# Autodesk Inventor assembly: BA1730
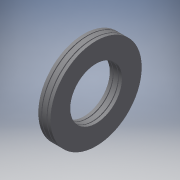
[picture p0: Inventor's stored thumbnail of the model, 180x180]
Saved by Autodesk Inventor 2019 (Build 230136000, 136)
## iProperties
Category: PARTsolutions
Company: MISUMI
Created: 2023-09
Part Number: BA1730
Catalog Web Link: www.cadenas.de
Description: BA_ _ _ _ _-Thrust Needle Roller Bearings with Retainers
Vendor: MISUMI
Document SubType Name: Assembly
Designer: psAdmin
Manufacturer: MISUMI
Mass: 1.86807 g
Surface Area: 34.7146 cm^2
Volume: 1.86807 cm^3
Density: 1 g/cm^3
Title: BA1730
Author: Cadenas PARTsolutions
Comments: Thrust Needle Roller Bearings with Retainers
PSOL_IDENT_0: {$CADENAS_DATA/23d-libs/misumi/metric/12_bearing_holders/ba1024_asmtab.prj},171 {VTYP=3D},{STYP=ASST
PSOL_IDENT_1: AB},{NB=BA1730},{LINA=BA1730},{NN=BA_ _ _ _ _},{DATE=03.06.2021 05:35:41},{GEOMDATE=19.10.2020 19:34
PSOL_IDENT_2: :04},{VERSION=},{LINEID=40},{WBVAR=},{WBNUMERIC=}  {NB=BA1730},{LINA=BA1730},{KT=DUMMY},{PN=BA1730},
PSOL_IDENT_3: {DD=17},{D=30},{B=2},{F=29.0},{F1=19.0},{DD1=17},{D1=30},{B1=1},{PPATH=ba1024_asmtpl.prj}
NB: BA1730
NN: BA_ _ _ _ _
NT: Thrust Needle Roller Bearings with Retainers
NBSYN: $PN.
LINA: BA1730
CATALOG: Misumi
PN: BA1730
DD: 17
D: 30
B: 2
F: 29
F1: 19
DD1: 17
D1: 30
B1: 1
SUPPLIER: MISUMI
ARTICLENO: BA1730
BOMINFO: BA1730
CREATOR: CADENAS GmbH
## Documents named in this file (3)
- e:\temp\worker_COMMON_2\temp\tmp_3268_92_iBUlv\format_0\BA1730.iam
- e:\temp\worker_COMMON_2\temp\tmp_3268_92_iBUlv\format_0\core_BA1730.ipt
- e:\temp\worker_COMMON_2\temp\tmp_3268_92_iBUlv\format_0\washer_BA1730.ipt
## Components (3 placed, 2 different names)
1. core_BA1730:1 — core_to_washer_Z@1 <-> washer1_Z@2, core_to_washer_YZ@1 <-> washer1_YZ@2, core_to_washer1_XY@1 <-> washer2_XY@3, core_to_washer1_Z@1 <-> washer2_Z@3, core_to_washer1_YZ@1 <-> washer2_YZ@3
2. washer_BA1730:1 — core_to_washer_Z@1 <-> washer1_Z@2, core_to_washer_YZ@1 <-> washer1_YZ@2
3. washer_BA1730:2 — core_to_washer1_XY@1 <-> washer2_XY@3, core_to_washer1_Z@1 <-> washer2_Z@3, core_to_washer1_YZ@1 <-> washer2_YZ@3
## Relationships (5: Mate 3, Angle 2)
- core_to_washer_Z@1 <-> washer1_Z@2 [Mate]: core_BA1730:1 ↔ washer_BA1730:1
- core_to_washer_YZ@1 <-> washer1_YZ@2 [Angle]: core_BA1730:1 ↔ washer_BA1730:1
- core_to_washer1_XY@1 <-> washer2_XY@3 [Mate]: core_BA1730:1 ↔ washer_BA1730:2
- core_to_washer1_Z@1 <-> washer2_Z@3 [Mate]: core_BA1730:1 ↔ washer_BA1730:2
- core_to_washer1_YZ@1 <-> washer2_YZ@3 [Angle]: core_BA1730:1 ↔ washer_BA1730:2
